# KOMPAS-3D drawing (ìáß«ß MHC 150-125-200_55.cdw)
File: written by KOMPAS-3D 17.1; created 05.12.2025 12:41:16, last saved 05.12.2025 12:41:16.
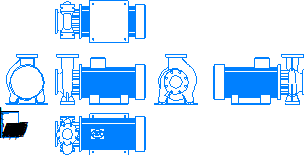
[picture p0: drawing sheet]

Sheet 1: A4, portrait

Title block, sheet 1: name: Насос MHC 150-125-200_55 / 55 кВт 3х380В; material: Сталь 10  ГОСТ 1050-88; mass: 842,83; sheets: 1; sheet format: A4

Views: Вид 1, Спереди, Проекционный вид 2, Проекционный вид 3, Проекционный вид 4, Проекционный вид 5, Проекционный вид 6
Referenced files in \\adlc.lan\data\АДЛ_ПКД\3D-модели\ADL production\Насосы ГРАНПАМП\Насосы ГРАНПАМП серии МНС\KOMPAS 3D\: Насос MHC 150-125-200_55.m3d
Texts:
  Andrey
  АДЛ
Dimensions and other numbers on the sheet: 1:1; 1; 55 кВт 3х380В; 842,83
